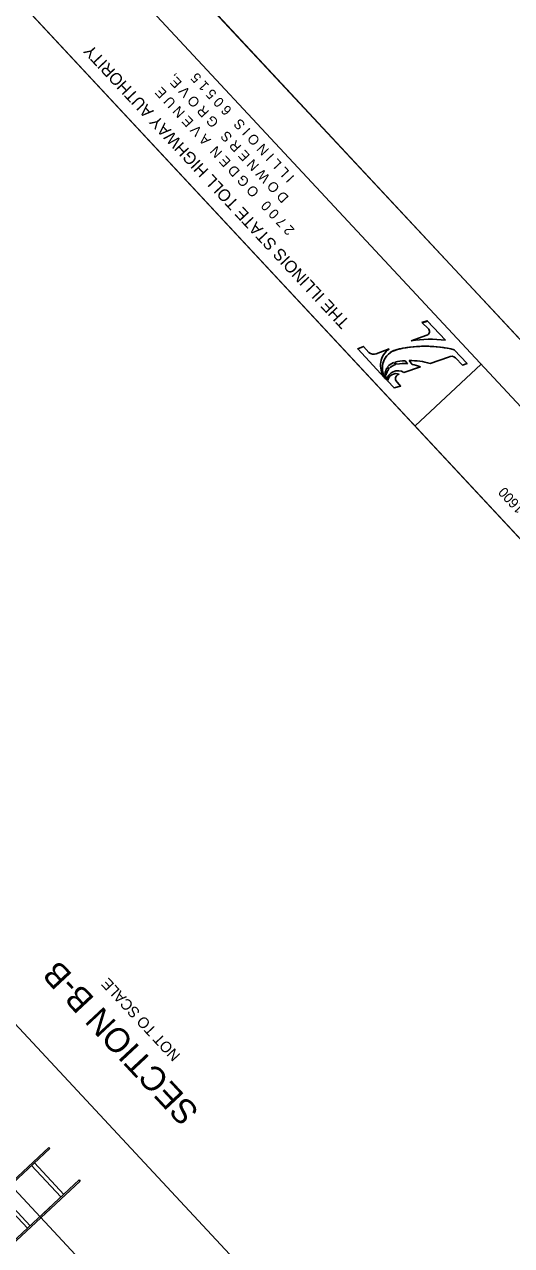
# Model space of a CAD drawing. Extents: x 1121979 to 1130574, y 1838676 to 1848573.
# Drawn here: x 1129657.38 to 1129668.15, y 1839365.55 to 1839392.53 of the extents above; entities that cross this region are included whole.
import ezdxf

# ---------------------------------------------------------------- set-up
doc = ezdxf.new("R2010")
doc.units = 0
for name, color, linetype in [('CLB-6', 7, 'Continuous'), ('GE-LOG-JEG', 7, 'Continuous'), ('GE-NOT-Notes', 7, 'Continuous'), ('GE-SHT-Clip Border', 7, 'Continuous'), ('GE-SHT-General', 7, 'Continuous'), ('GE-SHT-Plot Border', 7, 'Continuous'), ('HS_Dimensions and Text', 7, 'Continuous'), ('IPDC BUILDING RELATED', 7, 'Continuous'), ('IPDC-EXIST ELECT EQUIP', 7, 'Continuous'), ('Sheets_General Details', 7, 'Continuous')]:
    doc.layers.add(name, color=color, linetype=linetype)

# ---------------------------------------------------------------- blocks, each defined once
blk = doc.blocks.new('CLB_61')
at = {"layer": 'CLB-6'}
for p, q in [((0.095, 18.288), (0, 18.288)), ((0, 18.288), (0, 0)), ((0.095, 18.288), (0.095, 0)), ((3.048, 18.288), (2.953, 18.288)), ((2.953, 18.288), (2.953, 0)), ((3.048, 18.288), (3.048, 0)), ((0.095, 16.891), (2.953, 16.891)), ((0.095, 16.637), (2.953, 16.637)), ((0.098, 15.621), (0.098, 14.859)), ((0.095, 13.843), (2.953, 13.843)), ((0.095, 13.589), (2.953, 13.589)), ((0.095, 10.795), (2.953, 10.795)), ((0.095, 10.541), (2.953, 10.541)), ((0.095, 7.747), (2.953, 7.747)), ((0.095, 7.493), (2.953, 7.493)), ((0.095, 4.699), (2.953, 4.699)), ((0.095, 4.445), (2.953, 4.445)), ((0.098, 3.429), (0.098, 2.667)), ((2.95, 2.667), (2.95, 3.429)), ((0.095, 1.651), (2.953, 1.651)), ((0.095, 1.397), (2.953, 1.397)), ((0.095, 0), (0, 0)), ((3.048, 0), (2.953, 0))]:
    blk.add_line(p, q, dxfattribs=at)

msp = doc.modelspace()

# ---------------------------------------------------------------- linework, layer by layer
at = {"layer": 'GE-NOT-Notes'}
msp.add_line((1129686.907, 1839365.651), (1129640.533, 1839415.386), dxfattribs=at)
at = {"layer": 'GE-SHT-Clip Border'}
msp.add_lwpolyline([(1129652.729, 1839339.252), (1129609.766, 1839385.33), (1129639.021, 1839412.608), (1129681.985, 1839366.531)], close=True, dxfattribs=at)
msp.add_lwpolyline([(1129652.729, 1839339.252), (1129609.766, 1839385.33), (1129639.021, 1839412.608), (1129681.985, 1839366.531)], close=True, dxfattribs=at)
msp.add_lwpolyline([(1129652.729, 1839339.252), (1129609.766, 1839385.33), (1129639.021, 1839412.608), (1129681.985, 1839366.531)], close=True, dxfattribs=at)
at = {"layer": 'GE-SHT-General'}
for p, q in [((1129639.021, 1839412.608), (1129681.985, 1839366.531)), ((1129666.167, 1839385.943), (1129666.304, 1839385.814)), ((1129666.289, 1839385.978), (1129666.172, 1839385.939)), ((1129666.289, 1839385.978), (1129666.172, 1839385.939)), ((1129666.172, 1839385.939), (1129666.304, 1839385.814)), ((1129666.276, 1839385.664), (1129665.927, 1839385.538)), ((1129666.276, 1839385.664), (1129665.927, 1839385.538)), ((1129665.154, 1839385.254), (1129665.441, 1839385.361)), ((1129665.154, 1839385.254), (1129665.441, 1839385.361)), ((1129665.439, 1839385.359), (1129665.423, 1839385.354)), ((1129665.67, 1839385.36), (1129665.503, 1839385.304)), ((1129665.67, 1839385.36), (1129665.503, 1839385.304)), ((1129665.431, 1839384.914), (1129665.397, 1839384.947)), ((1129665.397, 1839384.947), (1129665.431, 1839384.914)), ((1129665.408, 1839384.963), (1129665.442, 1839384.928)), ((1129665.442, 1839384.928), (1129665.408, 1839384.963)), ((1129665.582, 1839385.016), (1129665.537, 1839385.06)), ((1129665.537, 1839385.06), (1129665.582, 1839385.016)), ((1129665.568, 1839385.071), (1129665.612, 1839385.023)), ((1129665.612, 1839385.023), (1129665.568, 1839385.071)), ((1129666.135, 1839384.966), (1129665.768, 1839384.84)), ((1129665.768, 1839384.84), (1129666.135, 1839384.966)), ((1129665.848, 1839385.033), (1129665.794, 1839385.101)), ((1129665.794, 1839385.101), (1129665.848, 1839385.033)), ((1129665.883, 1839385.104), (1129665.95, 1839385.019)), ((1129665.95, 1839385.019), (1129665.883, 1839385.104)), ((1129667.477, 1839385.023), (1129666.014, 1839383.659)), ((1129666.755, 1839385.179), (1129666.349, 1839385.043)), ((1129666.349, 1839385.043), (1129666.755, 1839385.179)), ((1129665.353, 1839384.798), (1129665.372, 1839384.787)), ((1129665.372, 1839384.787), (1129665.353, 1839384.798)), ((1129665.37, 1839384.775), (1129665.353, 1839384.784)), ((1129665.353, 1839384.784), (1129665.37, 1839384.775)), ((1129665.391, 1839384.671), (1129665.362, 1839384.702)), ((1129665.362, 1839384.702), (1129665.391, 1839384.671))]:
    msp.add_line(p, q, dxfattribs=at)
msp.add_lwpolyline([(1129652.729, 1839339.252), (1129609.766, 1839385.33), (1129640.484, 1839413.972), (1129683.448, 1839367.895)], close=True, dxfattribs=at)
for points in [[(1129666.687, 1839385.552), (1129666.285, 1839385.982), (1129666.167, 1839385.943)], [(1129666.687, 1839385.552), (1129666.289, 1839385.978)], [(1129665.339, 1839384.726), (1129664.746, 1839385.363), (1129664.872, 1839385.415), (1129664.994, 1839385.285)], [(1129665.339, 1839384.726), (1129664.746, 1839385.363), (1129664.872, 1839385.415), (1129664.994, 1839385.285)], [(1129666.882, 1839385.343), (1129667.164, 1839385.043), (1129667.061, 1839385.003), (1129666.91, 1839385.162)], [(1129666.91, 1839385.162), (1129667.061, 1839385.003), (1129667.164, 1839385.043), (1129666.882, 1839385.343)], [(1129665.406, 1839384.655), (1129665.55, 1839384.5), (1129665.696, 1839384.541), (1129665.587, 1839384.662)], [(1129665.406, 1839384.655), (1129665.55, 1839384.5), (1129665.696, 1839384.541), (1129665.587, 1839384.662)]]:
    msp.add_lwpolyline(points, dxfattribs=at)
for centre, major_axis, start_param, end_param in [((1129666.243, 1839385.749), (-0.0627, 0.0672), 2.748274, 4.778639), ((1129666.243, 1839385.749), (-0.0627, 0.0672), 2.748274, 4.778639), ((1129666.421, 1839383.171), (-1.662, 1.783), 5.406509, 5.725199), ((1129666.421, 1839383.171), (-1.662, 1.783), 5.406509, 5.725199), ((1129665.096, 1839385.402), (-0.109, 0.117), 1.668859, 2.756381), ((1129665.096, 1839385.402), (-0.109, 0.117), 1.668859, 2.756381), ((1129665.702, 1839384.983), (-0.313, 0.335), 6.133068, 7.724792), ((1129665.702, 1839384.983), (-0.313, 0.335), 6.133068, 7.724792), ((1129665.721, 1839384.927), (-0.298, 0.319), 5.815604, 7.668169), ((1129665.721, 1839384.927), (-0.298, 0.319), 6.049523, 7.668169), ((1129666.319, 1839382.719), (-1.868, 2.003), 5.30723, 5.789422), ((1129666.319, 1839382.719), (-1.868, 2.003), 5.30723, 5.760913), ((1129666.825, 1839385.08), (-0.0829, 0.0889), 4.724541, 6.141846), ((1129666.825, 1839385.08), (-0.0829, 0.0889), 4.724541, 6.141846), ((1129665.649, 1839384.782), (-0.205, 0.22), 0.247612, 0.782179), ((1129665.649, 1839384.782), (-0.205, 0.22), 0.247612, 0.782179), ((1129665.649, 1839384.782), (-0.205, 0.22), 5.905232, 6.464865), ((1129665.649, 1839384.782), (-0.205, 0.22), 5.905232, 6.464865), ((1129665.677, 1839384.716), (-0.215, 0.231), 5.82746, 6.373688), ((1129665.677, 1839384.716), (-0.215, 0.231), 5.82746, 6.373688), ((1129665.948, 1839383.433), (-1.155, 1.239), 5.610341, 5.74783), ((1129665.948, 1839383.433), (-1.155, 1.239), 5.610341, 5.74783), ((1129665.582, 1839385.016), (-0.000103, 0.000111), 2.778112, 5.82746), ((1129665.582, 1839385.016), (-0.000103, 0.000111), 2.778112, 5.82746), ((1129665.799, 1839384.052), (-0.681, 0.73), 5.467666, 5.709716), ((1129665.799, 1839384.052), (-0.681, 0.73), 5.467666, 5.709716), ((1129665.948, 1839383.433), (-1.155, 1.239), 5.275424, 5.556828), ((1129665.948, 1839383.433), (-1.155, 1.239), 5.275424, 5.556828), ((1129665.799, 1839384.052), (-0.681, 0.73), 5.168596, 5.36343), ((1129665.799, 1839384.052), (-0.681, 0.73), 5.168596, 5.36343), ((1129665.649, 1839384.782), (-0.205, 0.22), 0.828976, 1.118665), ((1129665.649, 1839384.782), (-0.205, 0.22), 0.828976, 1.118665), ((1129665.677, 1839384.716), (-0.215, 0.231), 0.646438, 0.891716), ((1129665.677, 1839384.716), (-0.215, 0.231), 0.646438, 0.891716), ((1129665.677, 1839384.716), (-0.215, 0.231), 0.147373, 0.608451), ((1129665.677, 1839384.716), (-0.215, 0.231), 0.147373, 0.608451), ((1129665.639, 1839384.629), (-0.173, 0.186), 4.974356, 6.952603), ((1129665.639, 1839384.629), (-0.173, 0.186), 4.974356, 6.952603), ((1129665.604, 1839384.615), (-0.139, 0.149), 5.210385, 6.91808), ((1129665.604, 1839384.615), (-0.139, 0.149), 5.210385, 6.91808), ((1129665.69, 1839384.697), (-0.0759, 0.0814), 5.749177, 7.446257), ((1129665.69, 1839384.697), (-0.0759, 0.0814), 5.749177, 7.446257)]:
    msp.add_ellipse(centre, major_axis=major_axis, ratio=0.970585, start_param=start_param, end_param=end_param, dxfattribs=at)
at = {"layer": 'GE-SHT-Plot Border'}
msp.add_lwpolyline([(1129686.907, 1839365.651), (1129640.533, 1839415.386), (1129608.352, 1839385.379), (1129654.726, 1839335.645)], close=True, dxfattribs=at)
at = {"layer": 'IPDC BUILDING RELATED'}
msp.add_line((1129668.039, 1839358.794), (1129648.683, 1839379.557), dxfattribs=at)
at = {"layer": 'IPDC-EXIST ELECT EQUIP'}
msp.add_line((1129652.389, 1839371.914), (1129659.107, 1839364.708), dxfattribs=at)

# ---------------------------------------------------------------- block references
at = {"layer": 'IPDC-EXIST ELECT EQUIP', "xscale": 0.3332999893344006, "yscale": -0.3332999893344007, "rotation": 132.99714502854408}
msp.add_blockref('CLB_61', (1129654.153, 1839362.823), dxfattribs=at)

# ---------------------------------------------------------------- texts
at = {"layer": 'GE-LOG-JEG'}
msp.add_text('525 W. Monroe Suite 1600', height=0.22, rotation=132.9971, dxfattribs=at).set_placement((1129670.382, 1839379.768))
at = {"layer": 'GE-SHT-General'}
for s, height, p in [('THE ILLINOIS STATE TOLL HIGHWAY AUTHORITY', 0.264, (1129664.583, 1839385.965)), ('D O W N E R S   G R O V E,', 0.22004, (1129663.238, 1839388.713)), ('I L L I N O I S   6 0 5 1 5', 0.22004, (1129663.36, 1839389.163)), ('2 7 0 0   O G D E N  A V E N U E', 0.22004, (1129663.363, 1839387.998))]:
    msp.add_text(s, height=height, rotation=132.9972, dxfattribs=at).set_placement(p)
at = {"layer": 'HS_Dimensions and Text'}
msp.add_text('NOT TO SCALE', height=0.24, rotation=132.9971, dxfattribs=at).set_placement((1129660.84, 1839369.764))
at = {"layer": 'Sheets_General Details'}
msp.add_text('SECTION B-B', height=0.53756, rotation=132.9971, dxfattribs=at).set_placement((1129661.262, 1839368.526))

doc.saveas('drawing.dxf')
